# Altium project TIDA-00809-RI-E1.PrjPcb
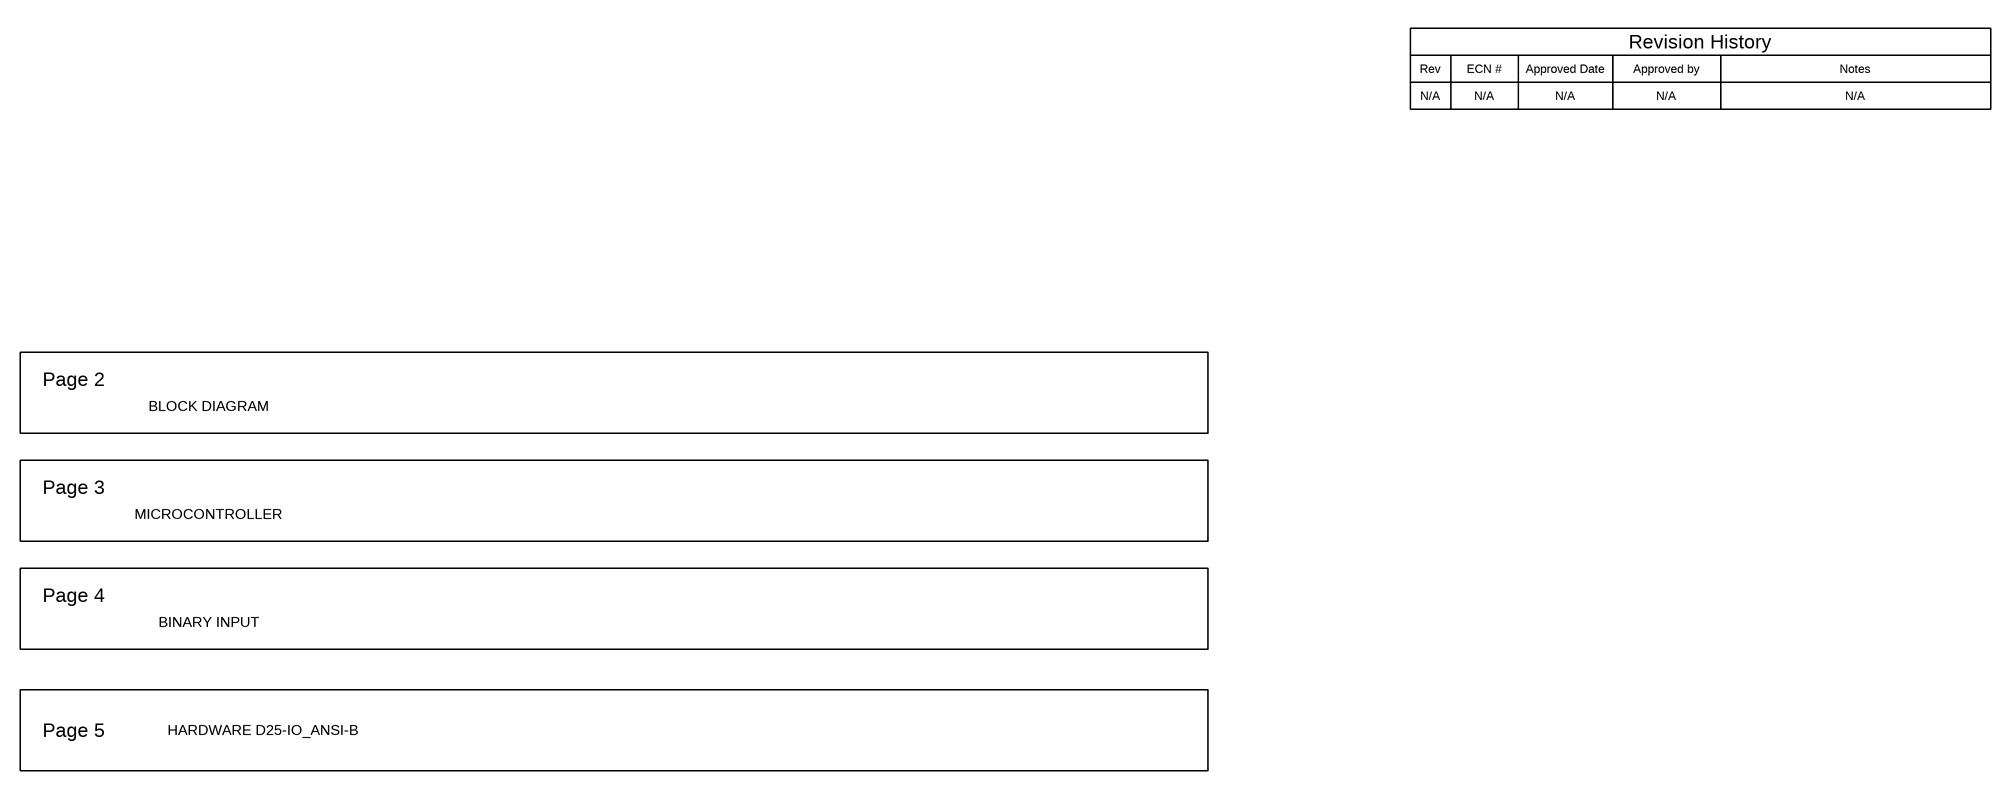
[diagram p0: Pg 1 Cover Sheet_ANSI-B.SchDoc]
TID: 00809-RI; TechSupport: http://www.ti.com/support; SCH_Rev: E1; PRJ_Title: AC/DC BINARY INPUT; PRJ_Number: TIDA-00809-RI; PRJ_Engineer: Sreenivas; PRJ_Customer: Public Release; PCB_Rev: E1; PCB_Layout: Avinash N; EVM_Orderable: N/A; CopyrightYear: 2016
5 sheets, 168 parts. Net scope: flat (ports and power ports of the same name join across sheets).
Board file: TIDA-00809-RI-E1.PcbDoc
Sheets:
  Pg 1 Cover Sheet_ANSI-B.SchDoc
  Pg2 Block Diagram.SchDoc
  Pg3 MICROCONTROLLER.SchDoc
  Pg 4 BINARY INPUTS.SchDoc
  Pg 5 Hardware_ANSI-B.SchDoc

## Sheet Pg 1 Cover Sheet_ANSI-B.SchDoc: Block Diagram
size 431 x 279 mm; Date: Not shown in title block; ApprovedBy: Not shown in title block; CheckedBy: Not shown in title block; Author: Not shown in title block; CompanyName: Not shown in title block; DrawnBy: Sreenivas; Engineer: Sreenivas; Organization: Not shown in title block; Address1: Not shown in title block; Address2: Not shown in title block; Address3: Not shown in title block; Address4: Not shown in title block; DocumentNumber: 1; Revision: Use project parameter SCH_Rev; SheetNumber: 1; SheetTotal: 5; PageSetup: Record=PageOptions¦CenterHorizontal=True¦CenterVertical=True¦PrintScale=1.00¦XCorrection=1.00¦YCorrection=1.00¦PrintKind=0¦BorderSize=5000000¦LeftOffset=0¦BottomOffset=0¦Orientation=2¦PaperLength=1000¦PaperWidth=1000¦Scale=100¦PaperSource=15¦PrintQuality=600¦MediaType=1¦DitherType=10¦PaperKind=Letter¦PrintScaleMode=1

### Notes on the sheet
- Rev
- N/A
- ECN #
- Approved Date
- Approved by
- Revision History
- Notes
- Page 2
- BLOCK DIAGRAM
- Page 3
- MICROCONTROLLER
- Page 4
- BINARY INPUT
- Page 5
- HARDWARE D25-IO_ANSI-B

## Sheet Pg2 Block Diagram.SchDoc: Block Diagram
size 431 x 279 mm; Date: Not shown in title block; ApprovedBy: Not shown in title block; CheckedBy: Not shown in title block; Author: Not shown in title block; CompanyName: Not shown in title block; DrawnBy: Sreenivas; Engineer: Sreenivas; Organization: Not shown in title block; Address1: Not shown in title block; Address2: Not shown in title block; Address3: Not shown in title block; Address4: Not shown in title block; DocumentNumber: 1; Revision: Use project parameter SCH_Rev; SheetNumber: 2; SheetTotal: 5; PageSetup: Record=PageOptions¦CenterHorizontal=True¦CenterVertical=True¦PrintScale=1.00¦XCorrection=1.00¦YCorrection=1.00¦PrintKind=0¦BorderSize=5000000¦LeftOffset=0¦BottomOffset=0¦Orientation=2¦PaperLength=1000¦PaperWidth=1000¦Scale=100¦PaperSource=15¦PrintQuality=600¦MediaType=1¦DitherType=10¦PaperKind=Letter¦PrintScaleMode=1
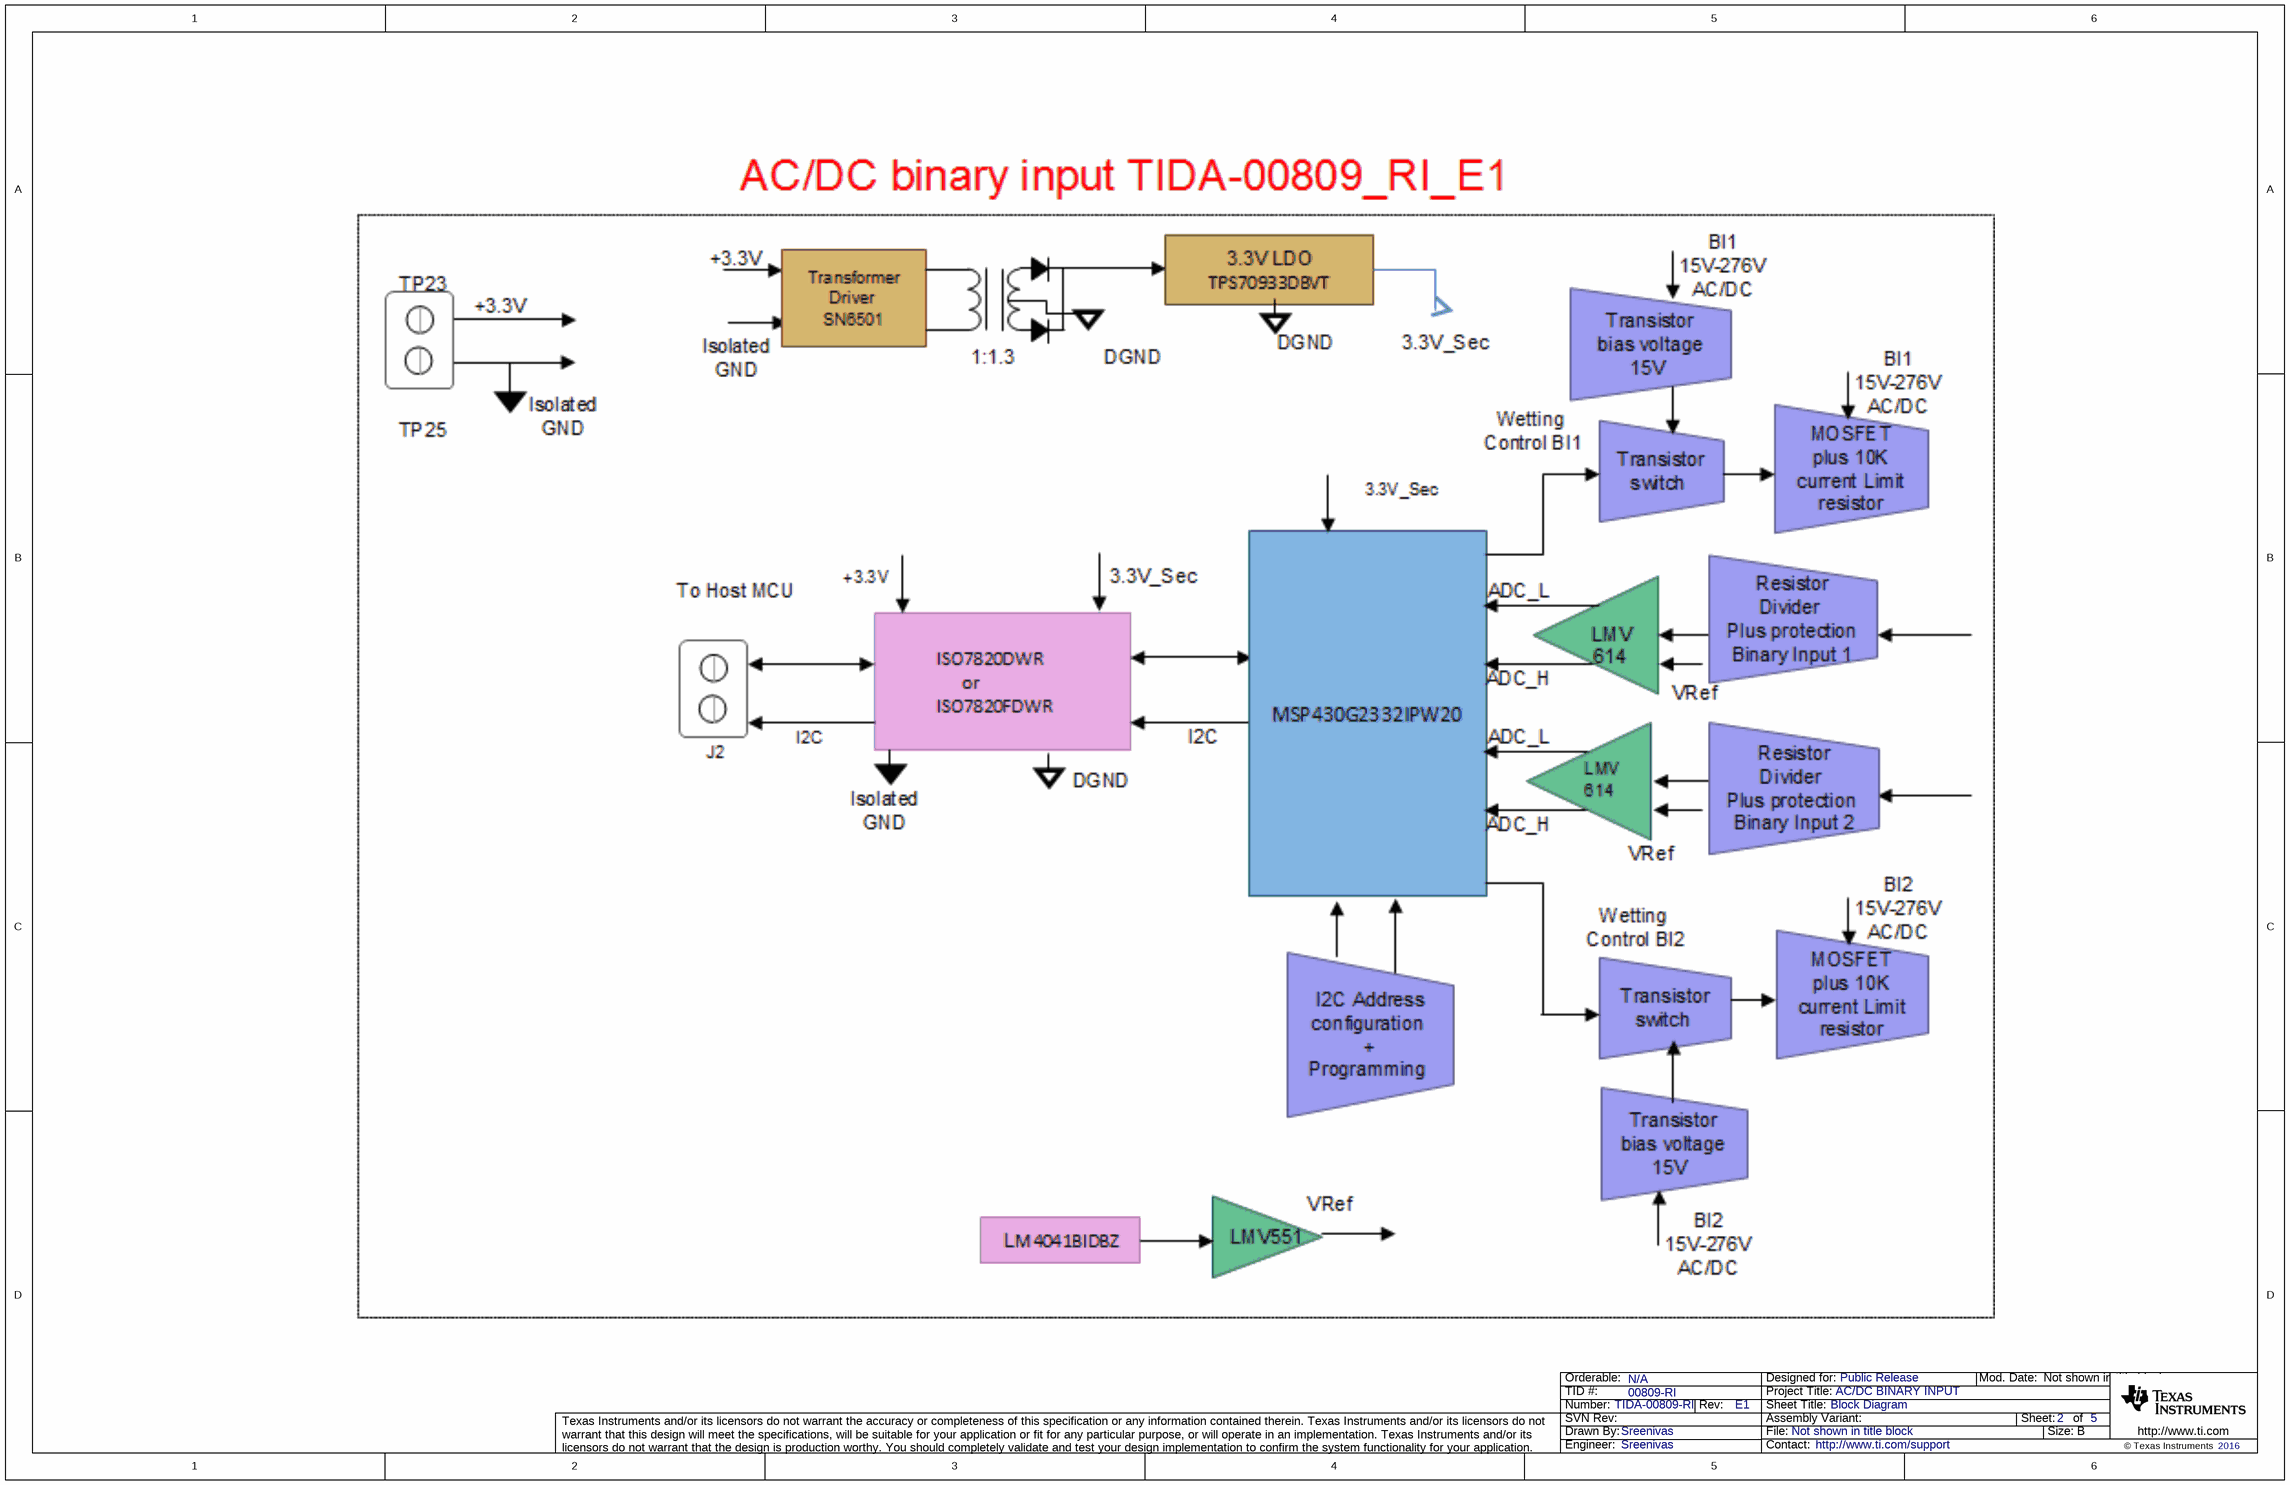
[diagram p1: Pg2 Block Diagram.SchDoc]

## Sheet Pg3 MICROCONTROLLER.SchDoc: Block Diagram
size 431 x 279 mm; Date: Not shown in title block; ApprovedBy: Not shown in title block; CheckedBy: Not shown in title block; Author: Not shown in title block; CompanyName: Not shown in title block; DrawnBy: Sreenivas; Engineer: Sreenivas; Organization: Not shown in title block; Address1: Not shown in title block; Address2: Not shown in title block; Address3: Not shown in title block; Address4: Not shown in title block; DocumentNumber: 1; Revision: Use project parameter SCH_Rev; SheetNumber: 3; SheetTotal: 5; PageSetup: Record=PageOptions¦CenterHorizontal=True¦CenterVertical=True¦PrintScale=1.00¦XCorrection=1.00¦YCorrection=1.00¦PrintKind=0¦BorderSize=5000000¦LeftOffset=0¦BottomOffset=0¦Orientation=2¦PaperLength=1000¦PaperWidth=1000¦Scale=100¦PaperSource=15¦PrintQuality=600¦MediaType=1¦DitherType=10¦PaperKind=Letter¦PrintScaleMode=1
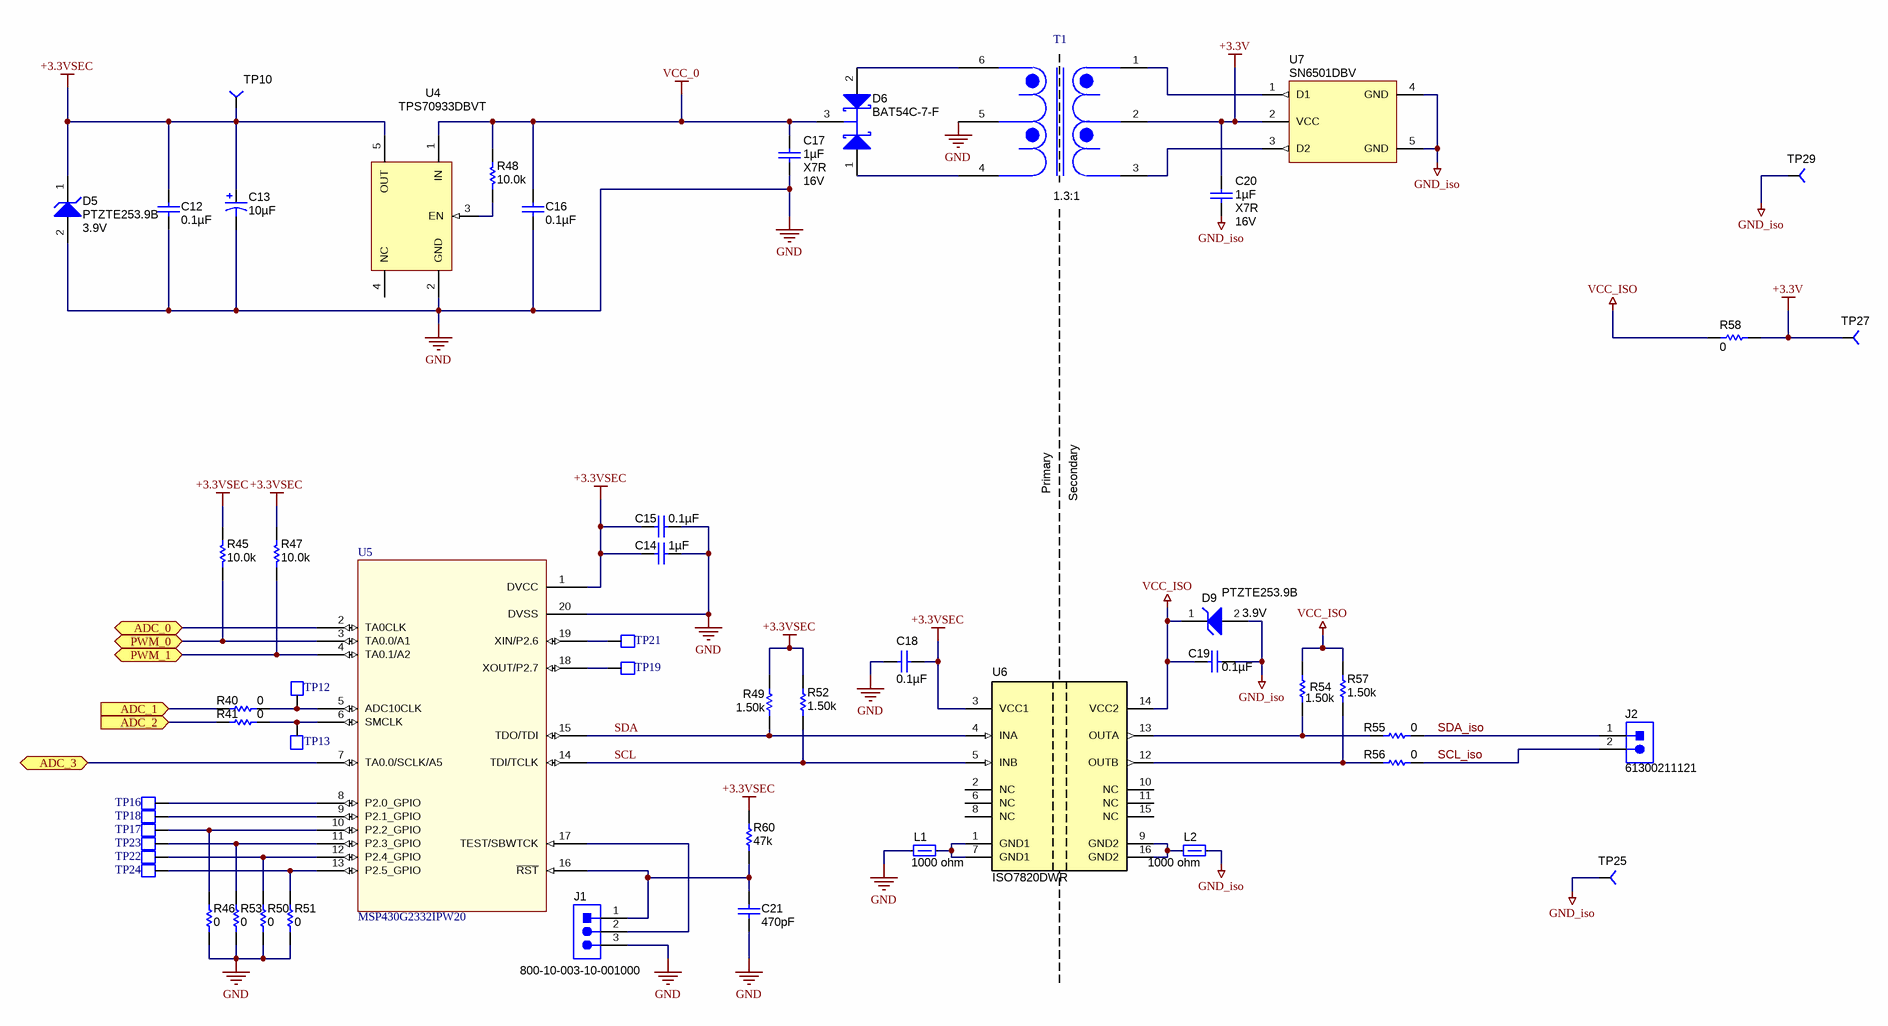
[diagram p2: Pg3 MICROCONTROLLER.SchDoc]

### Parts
C12  ValueDisplayed: 0.1µF  [0603]  (hidden comment: C0603C104K5RACTU)
C13  ValueDisplayed: 10µF  [3528-21]  (hidden comment: T491B106K016AT)
C14  ValueDisplayed: 1µF  [0603]  (hidden comment: C1608X7R1C105K)
C15  ValueDisplayed: 0.1µF  [0603]  (hidden comment: C0603C104K5RACTU)
C16  ValueDisplayed: 0.1µF  [0603]  (hidden comment: C0603C104K5RACTU)
C17  ValueDisplayed: 1µF  Value2: 16V  TempCo: X7R  [0603]  (hidden comment: C1608X7R1C105K)
C18  ValueDisplayed: 0.1µF  [0603]  (hidden comment: C0603C104K5RACTU)
C19  ValueDisplayed: 0.1µF  [0603]  (hidden comment: C0603C104K5RACTU)
C20  ValueDisplayed: 1µF  Value2: 16V  TempCo: X7R  [0603]  (hidden comment: C1608X7R1C105K)
C21  ValueDisplayed: 470pF  [0603]  (hidden comment: GRM188R71H471KA01D)
D5  PTZTE253.9B  value 3.9V  [SMA]
D6  BAT54C-7-F  [SOT-23]
D9  PTZTE253.9B  value 3.9V  [SMA]
J1  800-10-003-10-001000  [Mill-Max_800-10-003-10-001000]
J2  61300211121  [WURTH_61300211121]
L1  value 1000 ohm  [1206]  (hidden comment: HZ1206D102R-10)
L2  value 1000 ohm  [1206]  (hidden comment: HZ1206D102R-10)
R40  ValueDisplayed: 0  [0603]  (hidden comment: CRCW06030000Z0EA)
R41  ValueDisplayed: 0  [0603]  (hidden comment: CRCW06030000Z0EA)
R45  value 10.0k  [0603]  (hidden comment: CRCW060310K0FKEA)
R46  ValueDisplayed: 0  [0402]  (hidden comment: RC0402JR-070RL)
R47  value 10.0k  [0603]  (hidden comment: CRCW060310K0FKEA)
R48  value 10.0k  [0603]  (hidden comment: CRCW060310K0FKEA)
R49  value 1.50k  [0603]  (hidden comment: CRCW06031K50FKEA)
R50  ValueDisplayed: 0  [0402]  (hidden comment: RC0402JR-070RL)
R51  ValueDisplayed: 0  [0402]  (hidden comment: RC0402JR-070RL)
R52  value 1.50k  [0603]  (hidden comment: CRCW06031K50FKEA)
R53  ValueDisplayed: 0  [0402]  (hidden comment: RC0402JR-070RL)
R54  value 1.50k  [0603]  (hidden comment: CRCW06031K50FKEA)
R55  ValueDisplayed: 0  [0603]  (hidden comment: CRCW06030000Z0EA)
R56  ValueDisplayed: 0  [0603]  (hidden comment: CRCW06030000Z0EA)
R57  value 1.50k  [0603]  (hidden comment: CRCW06031K50FKEA)
R58  ValueDisplayed: 0  [0603]  (hidden comment: CRCW06030000Z0EA)
R60  ValueDisplayed: 47k  [0603]  (hidden comment: RC0603JR-0747KL)
T1  (no value)  [Wurth_750313734]
TP10  TP1_PD40_D0.5_S50  [TP1_PD40_D0.5_S50]  (value not drawn)
TP12  PAD_230UM  [PAD_230UM]  (value not drawn)
TP13  PAD_230UM  [PAD_230UM]  (value not drawn)
TP16  PAD_230UM  [PAD_230UM]  (value not drawn)
TP17  PAD_230UM  [PAD_230UM]  (value not drawn)
TP18  PAD_230UM  [PAD_230UM]  (value not drawn)
TP19  PAD_230UM  [PAD_230UM]  (value not drawn)
TP21  PAD_230UM  [PAD_230UM]  (value not drawn)
TP22  PAD_230UM  [PAD_230UM]  (value not drawn)
TP23  PAD_230UM  [PAD_230UM]  (value not drawn)
TP24  PAD_230UM  [PAD_230UM]  (value not drawn)
TP25  TP-5001-BLACK  [TH-40]  (value not drawn)
TP27  TP-5001-BLACK  [TH-40]  (value not drawn)
TP29  TP-5001-BLACK  [TH-40]  (value not drawn)
U4  TPS70933DBVT  [DBV0005A_N]
U5  MSP430G2332IPW20  [PW0020A_N]
U6  ISO7820DWR  [DW0016B_N]
U7  SN6501DBV  [DBV0005A_N]

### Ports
ADC_0 (bidir), ADC_1 (in), ADC_2 (in), ADC_3 (bidir), PWM_0 (bidir), PWM_1 (bidir)

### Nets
+3.3V: C20.1 R58.2 T1.2 TP27.1 U7.2(VCC)
+3.3VSEC: C12.1 C13.1(+) C14.1 C15.2 C18.2 D5.1(K) R45.2 R47.2 R49.2 R52.2 R60.2 TP10.1 U4.5(OUT) U5.1(DVCC) U6.3(VCC1)
GND: C12.2 C13.2(-) C14.2 C15.1 C16.2 C17.2 C18.1 C21.2 D5.2(A) J1.3 L1.1 R46.1 R50.1 R51.1 R53.1 T1.5 U4.2(GND) U5.20(DVSS)
GND_iso: C19.2 C20.2 D9.2(A) L2.2 TP25.1 TP29.1 U7.4(GND) U7.5(GND)
VCC_0: C16.1 C17.1 D6.3(K) R48.2 U4.1(IN)
VCC_ISO: C19.1 D9.1(K) R54.2 R57.2 R58.1 U6.14(VCC2)
ADC_0: U5.2(TA0CLK) ; port ADC_0
ADC_1: R40.1 ; port ADC_1
ADC_2: R41.1 ; port ADC_2
ADC_3: U5.7(TA0.0/SCLK/A5) ; port ADC_3
PWM_0: R45.1 U5.3(TA0.0/A1) ; port PWM_0
PWM_1: R47.1 U5.4(TA0.1/A2) ; port PWM_1
SCL: R52.1 U5.14(TDI/TCLK) U6.5(INB)
SCL_iso: J2.2 R56.2
SDA: R49.1 U5.15(TDO/TDI) U6.4(INA)
SDA_iso: J2.1 R55.2
NetC21_1: C21.1 J1.1 R60.1 U5.16(~{RST})
NetD6_1: D6.1(A1) T1.4
NetD6_2: D6.2(A2) T1.6
NetJ1_2: J1.2 U5.17(TEST/SBWTCK)
NetL1_2: L1.2 U6.1(GND1) U6.7(GND1)
NetL2_1: L2.1 U6.9(GND2) U6.16(GND2)
NetR40_2: R40.2 TP12.1 U5.5(ADC10CLK)
NetR41_2: R41.2 TP13.1 U5.6(SMCLK)
NetR46_2: R46.2 TP17.1 U5.10(P2.2_GPIO)
NetR48_1: R48.1 U4.3(EN)
NetR50_2: R50.2 TP22.1 U5.12(P2.4_GPIO)
NetR51_2: R51.2 TP24.1 U5.13(P2.5_GPIO)
NetR53_2: R53.2 TP23.1 U5.11(P2.3_GPIO)
NetR54_1: R54.1 R55.1 U6.13(OUTA)
NetR56_1: R56.1 R57.1 U6.12(OUTB)
NetT1_1: T1.1 U7.1(D1)
NetT1_3: T1.3 U7.3(D2)
NetTP16_1: TP16.1 U5.8(P2.0_GPIO)
NetTP18_1: TP18.1 U5.9(P2.1_GPIO)
NetTP19_1: TP19.1 U5.18(XOUT/P2.7)
NetTP21_1: TP21.1 U5.19(XIN/P2.6)

Not connected (* = marked no-connect by the designer): U4 4(NC); U6 2(NC) 6(NC) 8(NC) 10(NC) 11(NC) 15(NC)

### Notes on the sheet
- (near T1) 1.3:1
- Primary
- Secondary

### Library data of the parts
C12 C15 C16 C18 C19 = C0603C104K5RACTU: CAP, CERM, 0.1uF, 50V, +/-10%, X7R, 0603; Manufacturer: Kemet; Polarized: N; CompType: Capacitor; U/M: EA; Cap_F: 0.0000001; Tolerance_%: 10; Value1: Unknown; VDC_V: 50; TaMin_C: -55; TaMax_C: 125
C13 = 293D106X9016B2TE3: CAP, TA, 10 µF, 16 V, +/- 10%, 2 ohm, SMD; Manufacturer: Vishay-Sprague; Polarized: Y; CompType: Capacitor; Value: 10uF; U/M: EA; Cap_F: 0.00001; Tolerance_%: 10; Value1: 2 ohm; VDC_V: 16; Value2: 16V; ESR_ohm: 2; IRMS_A: 0.21; TaMin_C: -55; TaMax_C: 125; Cap_Case: B
C14 C17 C20 = C1608X7R1C105K: CAP, CERM, 1uF, 16V, +/-10%, X7R, 0603; Manufacturer: TDK; Polarized: N; CompType: Capacitor; U/M: EA; Cap_F: 0.000001; Tolerance_%: 10; ESR_Ohm: 0.0057; Value1: 0.0057 ohm; VDC_V: 16; TaMin_C: -55; TaMax_C: 125
C21 = GRM188R71H471KA01D: CAP, CERM, 470 pF, 50 V, +/- 10%, X7R, 0603; Manufacturer: MuRata; Polarized: N; CompType: Capacitor; Value: 470pF; U/M: EA; Cap_F: 0.00000000047; Tolerance_%: 10; Value1: Unknown; VDC_V: 50; Value2: 50V; TaMin_C: -55; TaMax_C: 125
D5 D9 = PTZTE255.6B: DIODE ZENER 4.1V 1W PMDS; Manufacturer: Rohm Semiconductor; U/M: EA; Vz_V: 3.9
D6 = BAT54C-7-F: Diode, Schottky, 30V, 0.2A, SOT-23; Manufacturer: Diodes Inc.; U/M: EA; Vf_V: 0.65; Value2: 0.65V; Io_A: 0.2; Vr_V: 30; TJmax_C: 125
J1 = 800-10-003-10-001000: Header, 100mil, 3x1, TH; Manufacturer: Mill-Max; SymbolCreator: a0799628; U/M: EA
J2 = 61300211121: Header, 2.54 mm, 2x1, Gold, TH; Manufacturer: Wurth Elektronik; SymbolCreator: a0412235
L1 L2 = HZ1206D102R-10: Ferrite Bead, 1000 ohm @ 100 MHz, 0.4 A, 1206; Manufacturer: Laird-Signal Integrity Products; Imax_A: 0.4; Value1: 0.4 ohm; Value2: 0.4A; ZTyp@100MHz_Ohm: 1000; Ztyp@1GHz_Ohm: 100
R40 R41 R55 R56 R58 = CRCW06030000Z0EA: RES, 0, 5%, 0.1 W, 0603; Manufacturer: Vishay-Dale; CompType: Resistor; Value: 0; Value_Code: 0000; Tolerance_%: 5; Power_W: 0.1; Value2: 0.1W; VDC_V: 75; TempCo: 200 ppm/C; EIA_Code: E24; U/M: EA
R45 R47 R48 = CRCW060310K0FKEA: RES, 10.0k ohm, 1%, 0.1W, 0603; Manufacturer: Vishay-Dale; CompType: Resistor; Res_ohm: 10000; Value_Code: 10k0; Tolerance_%: 1; Power_W: 0.1; VDC_V: 75; TempCo: 100 ppm/C; EIA_Code: E96; U/M: EA
R46 R50 R51 R53 = CRCW06030000Z0EA: RES, 0, 5%, 0.063 W, 0402; Manufacturer: Yageo; CompType: Resistor; Value: 0; Value_Code: 0000; Tolerance_%: 5; Power_W: 0.1; Value2: 0.1W; VDC_V: 75; TempCo: 200 ppm/C; EIA_Code: E24; U/M: EA
R49 R52 R54 R57 = CRCW06031K50FKEA: RES, 1.50k ohm, 1%, 0.1W, 0603; Manufacturer: Vishay-Dale; CompType: Resistor; Res_ohm: 1500; Value_Code: 1k50; Tolerance_%: 1; Power_W: 0.1; VDC_V: 75; TempCo: 100 ppm/C; EIA_Code: E96; U/M: EA
R60 = RC0603JR-0747KL: RES, 47 k, 5%, 0.1 W, 0603; Manufacturer: Yageo America; CompType: Resistor; Value: 47k; Res_ohm: 47000; Value_Code: 47k0; Tolerance_%: 5; Power_W: 0.1; Value2: 0.1W; VDC_V: 50; TempCo: 100 ppm/C; EIA_Code: E24; U/M: EA
T1 = 750313734_TRANSFORMER: TRANSFORMER SMD; Manufacturer: Wurth Electronics Midcom; PartNumber: 750313638
TP10 = TP-040_RND: Test Point 40mil pad 20mil drill; Manufacturer: STD; Value: STD
TP12 TP13 TP16-TP19 TP21-TP24 = PAD_230UM: Pad, SMT 0.23 mm; Area: 13200
TP25 TP27 TP29 = TP-5001-BLACK: Test Point,  Black, Thru Hole Color Keyed; Manufacturer: Keystone; PartNumber: 5001; area: 10.000; Value: 5001
U4 = TPS70933DBVT: IC REG LDO 3.3V 0.15A SOT23-5; Alternate Manufacturer: None; Manufacturer: Texas Instruments; SymbolCreator: a0411947; U/M: EA
U5 = MSP430G2332IPW20: IC MCU 16BIT 4KB FLASH 20TSSOP; Manufacturer: TI; Comp Type: Microcontroller
U6 = ISO7820DWR: High-Performance, 8000 VPK Reinforced Dual Channel Digital Isolator, DW0016B; Manufacturer: Texas Instruments; SymbolCreator: Altium; CompType: IC; U/M: EA
U7 = SN6501DBV: Transformer Driver for Isolated Power Supplies, DBV0005A; Alternate Manufacturer: None; Manufacturer: Texas Instruments; SymbolCreator: a0411947; CompType: IC; U/M: EA

## Sheet Pg 4 BINARY INPUTS.SchDoc: Block Diagram
size 431 x 279 mm; Date: Not shown in title block; ApprovedBy: Not shown in title block; CheckedBy: Not shown in title block; Author: Not shown in title block; CompanyName: Not shown in title block; DrawnBy: Sreenivas; Engineer: Sreenivas; Organization: Not shown in title block; Address1: Not shown in title block; Address2: Not shown in title block; Address3: Not shown in title block; Address4: Not shown in title block; DocumentNumber: 1; Revision: Use project parameter SCH_Rev; SheetNumber: 4; SheetTotal: 5; PageSetup: Record=PageOptions¦CenterHorizontal=True¦CenterVertical=True¦PrintScale=1.00¦XCorrection=1.00¦YCorrection=1.00¦PrintKind=0¦BorderSize=5000000¦LeftOffset=0¦BottomOffset=0¦Orientation=2¦PaperLength=1000¦PaperWidth=1000¦Scale=100¦PaperSource=15¦PrintQuality=600¦MediaType=1¦DitherType=10¦PaperKind=Letter¦PrintScaleMode=1
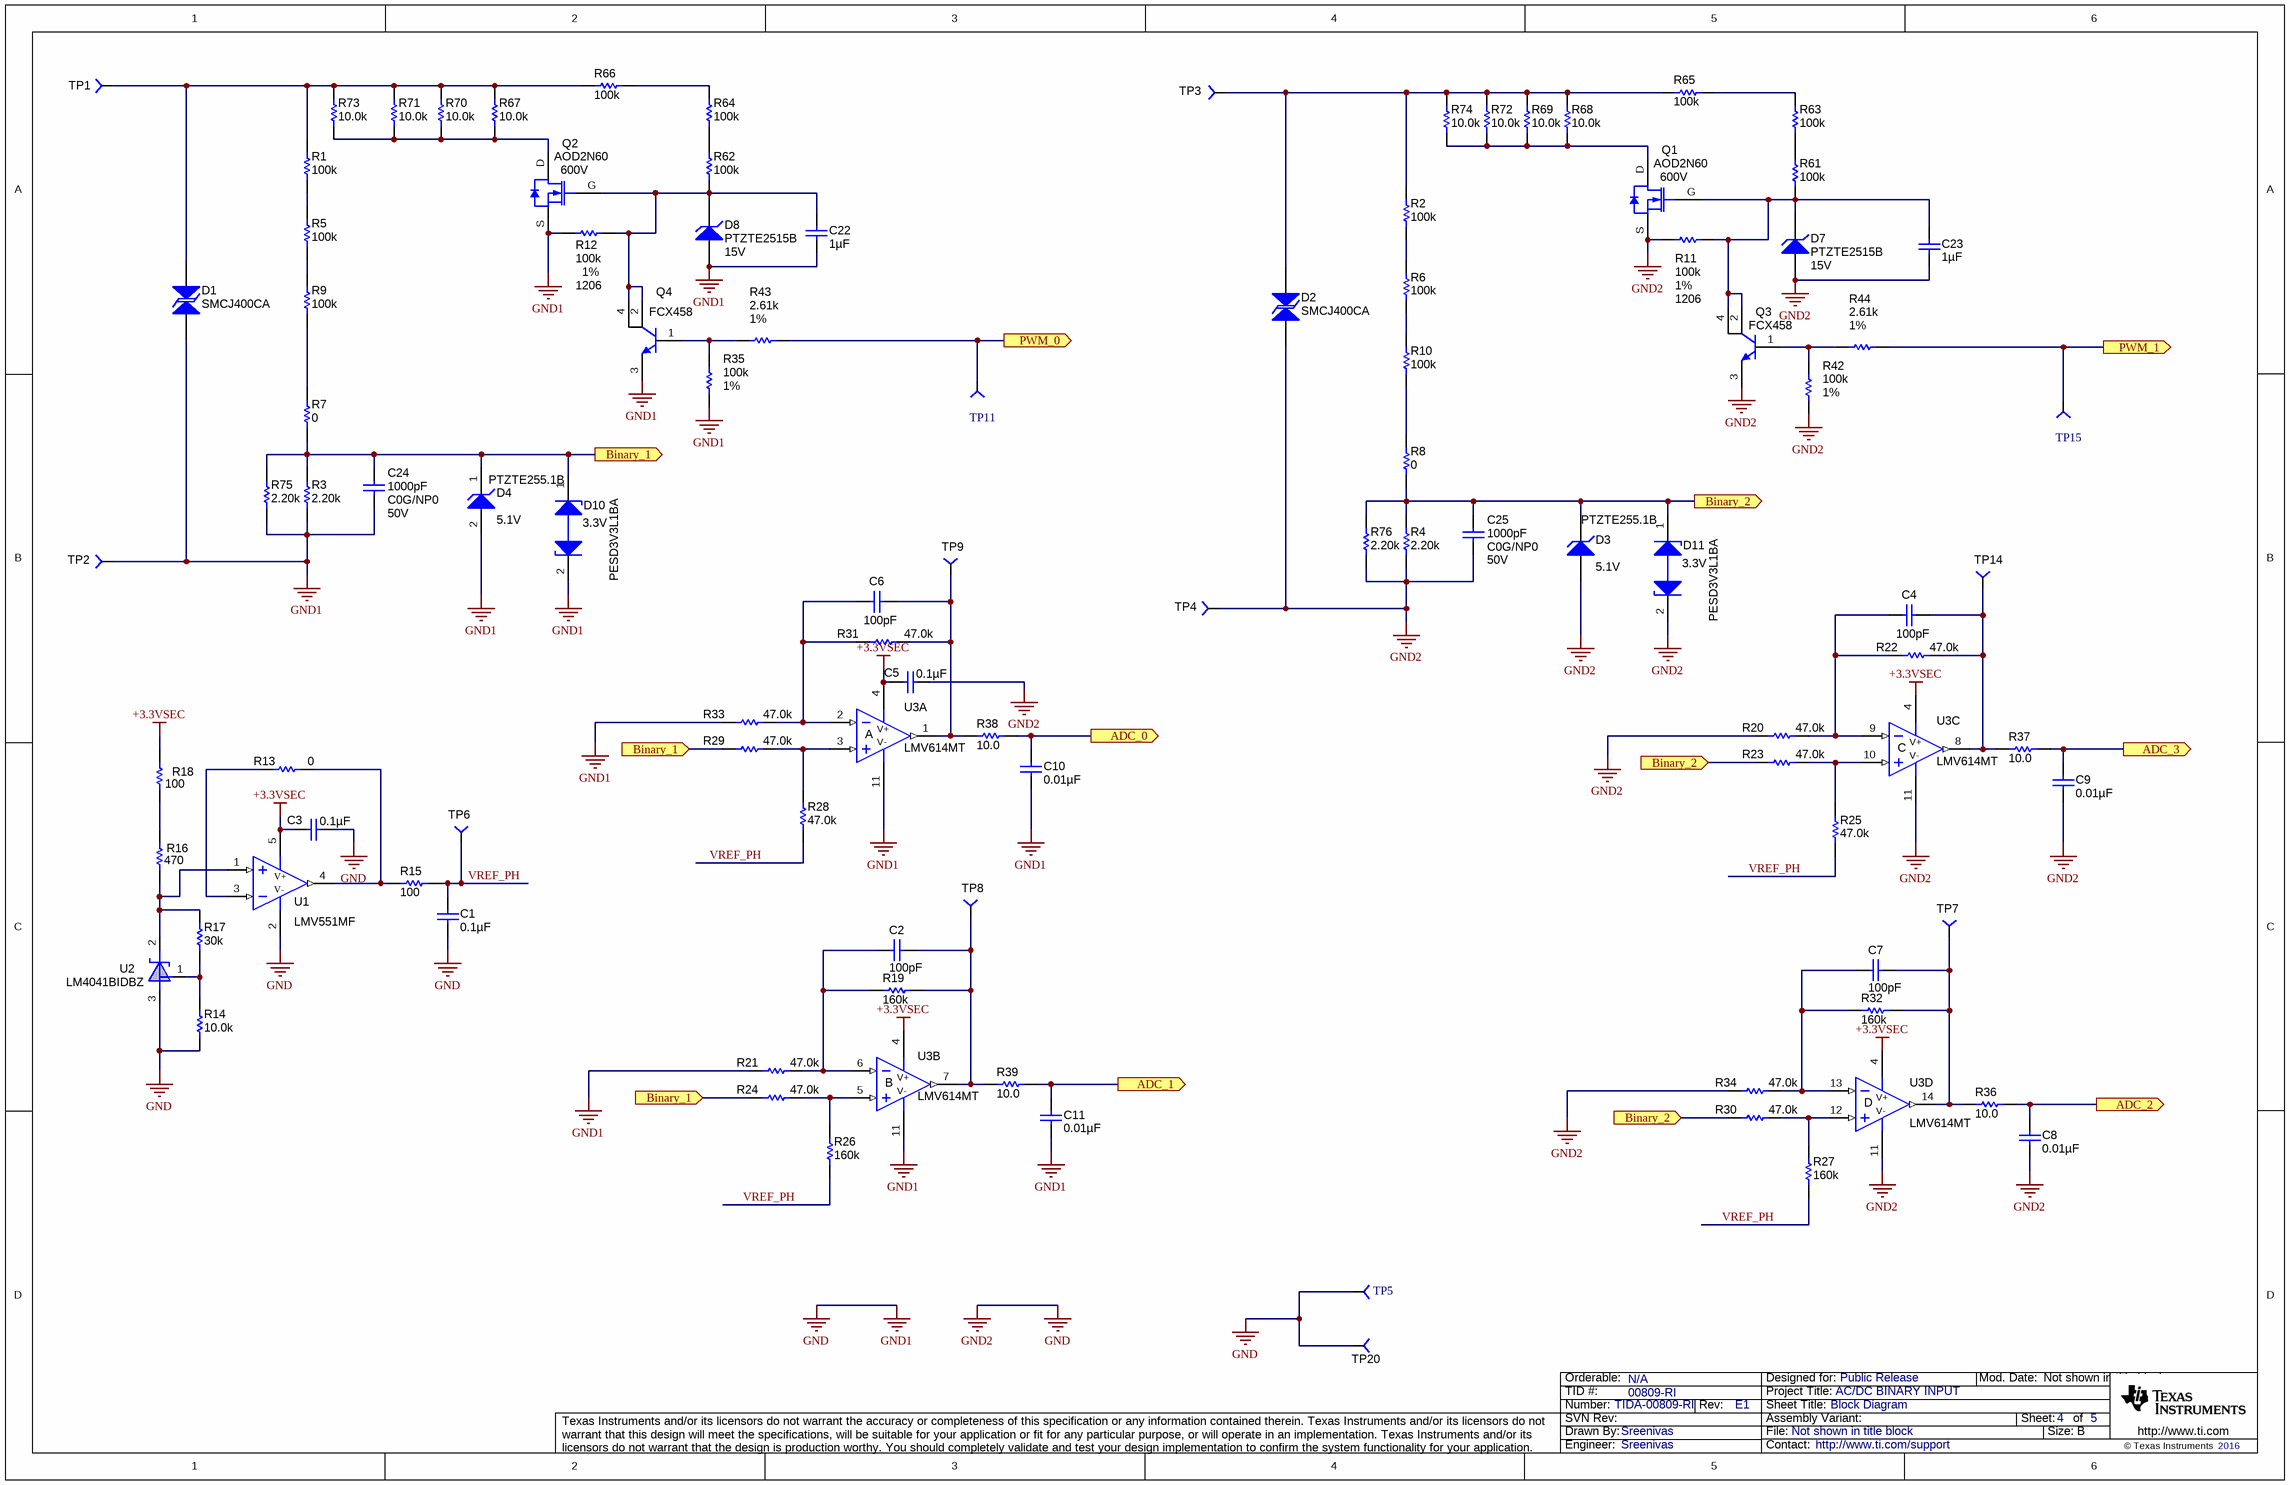
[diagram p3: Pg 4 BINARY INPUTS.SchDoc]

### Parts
C1  ValueDisplayed: 0.1µF  [0603]  (hidden comment: 06033C104JAT2A)
C2  ValueDisplayed: 100pF  [0603]  (hidden comment: 06035A101FAT2A)
C3  ValueDisplayed: 0.1µF  [0603]  (hidden comment: 06033C104JAT2A)
C4  ValueDisplayed: 100pF  [0603]  (hidden comment: 06035A101FAT2A)
C5  ValueDisplayed: 0.1µF  [0603]  (hidden comment: 06033C104JAT2A)
C6  ValueDisplayed: 100pF  [0603]  (hidden comment: 06035A101FAT2A)
C7  ValueDisplayed: 100pF  [0603]  (hidden comment: 06035A101FAT2A)
C8  ValueDisplayed: 0.01µF  [0603]  (hidden comment: C1608C0G1E103J)
C9  ValueDisplayed: 0.01µF  [0603]  (hidden comment: C1608C0G1E103J)
C10  ValueDisplayed: 0.01µF  [0603]  (hidden comment: C1608C0G1E103J)
C11  ValueDisplayed: 0.01µF  [0603]  (hidden comment: C1608C0G1E103J)
C22  ValueDisplayed: 1µF  [0603]  (hidden comment: UMK107AB7105KA-T)
C23  ValueDisplayed: 1µF  [0603]  (hidden comment: UMK107AB7105KA-T)
C24  ValueDisplayed: 1000pF  Value2: 50V  TempCo: C0G/NP0  [0603]  (hidden comment: C1608C0G1H102J)
C25  ValueDisplayed: 1000pF  Value2: 50V  TempCo: C0G/NP0  [0603]  (hidden comment: C1608C0G1H102J)
D1  SMCJ400CA  [SMC]
D2  SMCJ400CA  [SMC]
D3  PTZTE255.1B  value 5.1V  [SMA]
D4  PTZTE255.1B  value 5.1V  [SMA]
D7  PTZTE2515B  value 15V  [SMA]
D8  PTZTE2515B  value 15V  [SMA]
D10  PESD3V3L1BA  value 3.3V  [DIO_SOD323]
D11  PESD3V3L1BA  value 3.3V  [DIO_SOD323]
Q1  AOD2N60  value 600V  [DPAK_G]
Q2  AOD2N60  value 600V  [DPAK_G]
Q3  FCX458  [SOT-89-3]
Q4  FCX458  [SOT-89-3]
R1  ValueDisplayed: 100k  [1206]  (hidden comment: RC1206FR-07100KL)
R2  ValueDisplayed: 100k  [1206]  (hidden comment: RC1206FR-07100KL)
R3  ValueDisplayed: 2.20k  [0603]  (hidden comment: RC0603FR-072K2L)
R4  ValueDisplayed: 2.20k  [0603]  (hidden comment: RC0603FR-072K2L)
R5  ValueDisplayed: 100k  [1206]  (hidden comment: RC1206FR-07100KL)
R6  ValueDisplayed: 100k  [1206]  (hidden comment: RC1206FR-07100KL)
R7  ValueDisplayed: 0  [0603]  (hidden comment: RC0603JR-070RL)
R8  ValueDisplayed: 0  [0603]  (hidden comment: RC0603JR-070RL)
R9  ValueDisplayed: 100k  [1206]  (hidden comment: RC1206FR-07100KL)
R10  ValueDisplayed: 100k  [1206]  (hidden comment: RC1206FR-07100KL)
R11  value 100k  Value1: 1%  [1206]  (hidden comment: CRCW1206100KFKEA)
R12  value 100k  Value1: 1%  [1206]  (hidden comment: CRCW1206100KFKEA)
R13  ValueDisplayed: 0  [0603]  (hidden comment: RC0603JR-070RL)
R14  value 10.0k  [0603]  (hidden comment: CRCW060310K0FKEA)
R15  value 100  [0603]  (hidden comment: CRCW0603100RFKEA)
R16  value 470  [0603]  (hidden comment: CRCW0603470RJNEA)
R17  value 30k  [0603]  (hidden comment: CRCW060330K0JNEA)
R18  value 100  [0603]  (hidden comment: CRCW0603100RFKEA)
R19  ValueDisplayed: 160k  [0603]  (hidden comment: CRCW0603160KFKEA)
R20  ValueDisplayed: 47.0k  [0603]  (hidden comment: RC0603FR-0747KL)
R21  ValueDisplayed: 47.0k  [0603]  (hidden comment: RC0603FR-0747KL)
R22  ValueDisplayed: 47.0k  [0603]  (hidden comment: RC0603FR-0747KL)
R23  ValueDisplayed: 47.0k  [0603]  (hidden comment: RC0603FR-0747KL)
R24  ValueDisplayed: 47.0k  [0603]  (hidden comment: RC0603FR-0747KL)
R25  ValueDisplayed: 47.0k  [0603]  (hidden comment: RC0603FR-0747KL)
R26  ValueDisplayed: 160k  [0603]  (hidden comment: CRCW0603160KFKEA)
R27  ValueDisplayed: 160k  [0603]  (hidden comment: CRCW0603160KFKEA)
R28  ValueDisplayed: 47.0k  [0603]  (hidden comment: RC0603FR-0747KL)
R29  ValueDisplayed: 47.0k  [0603]  (hidden comment: RC0603FR-0747KL)
R30  ValueDisplayed: 47.0k  [0603]  (hidden comment: RC0603FR-0747KL)
R31  ValueDisplayed: 47.0k  [0603]  (hidden comment: RC0603FR-0747KL)
R32  ValueDisplayed: 160k  [0603]  (hidden comment: CRCW0603160KFKEA)
R33  ValueDisplayed: 47.0k  [0603]  (hidden comment: RC0603FR-0747KL)
R34  ValueDisplayed: 47.0k  [0603]  (hidden comment: RC0603FR-0747KL)
R35  value 100k  Value1: 1%  [0603]  (hidden comment: CRCW0603100KFKEA)
R36  ValueDisplayed: 10.0  [0603]  (hidden comment: CRCW060310R0FKEA)
R37  ValueDisplayed: 10.0  [0603]  (hidden comment: CRCW060310R0FKEA)
R38  ValueDisplayed: 10.0  [0603]  (hidden comment: CRCW060310R0FKEA)
R39  ValueDisplayed: 10.0  [0603]  (hidden comment: CRCW060310R0FKEA)
R42  value 100k  Value1: 1%  [0603]  (hidden comment: CRCW0603100KFKEA)
R43  value 2.61k  Value1: 1%  [0603]  (hidden comment: CRCW06032K61FKEA)
R44  value 2.61k  Value1: 1%  [0603]  (hidden comment: CRCW06032K61FKEA)
R61  ValueDisplayed: 100k  [1206]  (hidden comment: RC1206FR-07100KL)
R62  ValueDisplayed: 100k  [1206]  (hidden comment: RC1206FR-07100KL)
R63  ValueDisplayed: 100k  [1206]  (hidden comment: RC1206FR-07100KL)
R64  ValueDisplayed: 100k  [1206]  (hidden comment: RC1206FR-07100KL)
R65  ValueDisplayed: 100k  [1206]  (hidden comment: RC1206FR-07100KL)
R66  ValueDisplayed: 100k  [1206]  (hidden comment: RC1206FR-07100KL)
R67  ValueDisplayed: 10.0k  [1206]  (hidden comment: MCR18ERTF1002)
R68  ValueDisplayed: 10.0k  [1206]  (hidden comment: MCR18ERTF1002)
R69  ValueDisplayed: 10.0k  [1206]  (hidden comment: MCR18ERTF1002)
R70  ValueDisplayed: 10.0k  [1206]  (hidden comment: MCR18ERTF1002)
R71  ValueDisplayed: 10.0k  [1206]  (hidden comment: MCR18ERTF1002)
R72  ValueDisplayed: 10.0k  [1206]  (hidden comment: MCR18ERTF1002)
R73  ValueDisplayed: 10.0k  [1206]  (hidden comment: MCR18ERTF1002)
R74  ValueDisplayed: 10.0k  [1206]  (hidden comment: MCR18ERTF1002)
R75  ValueDisplayed: 2.20k  [0603]  (hidden comment: RC0603FR-072K2L)
R76  ValueDisplayed: 2.20k  [0603]  (hidden comment: RC0603FR-072K2L)
TP1  TP-5001-BLACK  [TH-40]  (value not drawn)
TP2  TP-5001-BLACK  [TH-40]  (value not drawn)
TP3  TP-5001-BLACK  [TH-40]  (value not drawn)
TP4  TP-5001-BLACK  [TH-40]  (value not drawn)
TP5  TP-040_RND  [TP-040_RND]  (value not drawn)
TP6  TP-040_RND  [TP-040_RND]  (value not drawn)
TP7  TP-040_RND  [TP-040_RND]  (value not drawn)
TP8  TP-040_RND  [TP-040_RND]  (value not drawn)
TP9  TP-040_RND  [TP-040_RND]  (value not drawn)
TP11  TP-040_RND  [TP-040_RND]  (value not drawn)
TP14  TP-040_RND  [TP-040_RND]  (value not drawn)
TP15  TP-040_RND  [TP-040_RND]  (value not drawn)
TP20  TP1_PD40_D0.5_S50  [TP1_PD40_D0.5_S50]  (value not drawn)
U1  LMV551MF  [MF05A_L]
U2  LM4041BIDBZ  [SOT-23]
U3  LMV614MT  [PW0014A_N]  (parts A,B,C,D of 4)

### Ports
ADC_0 (out), ADC_1 (out), ADC_2 (out), ADC_3 (out), Binary_1 (in), Binary_1 (out), Binary_2 (in), Binary_2 (out), PWM_0 (out), PWM_1 (out)

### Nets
+3.3VSEC: C3.2 C5.2 R18.1 U1.5(V+) U3.4(V+)
GND: C1.1 C3.1 C5.1 C8.1 C9.1 C10.1 C11.1 C22.1 C23.1 C24.1 C25.1 D1.1 D2.1 D3.2(A) D4.2(A) D7.2(A) D8.2(A) D10.2(K) D11.2(K) Q1.S Q2.S Q3.3(E) Q4.3(E) R3.1 R4.1 R11.1 R12.1 R14.1 R20.1 R21.1 R33.2 R34.1 R35.1 R42.1 R75.1 R76.1 TP2.1 TP4.1 TP5.1 TP20.1 U1.2(V-) U2.3(A) U3.11(V-)  [also labelled GND1, GND2]
ADC_0: C10.2 R38.2 ; port ADC_0
ADC_1: C11.2 R39.2 ; port ADC_1
ADC_2: C8.2 R36.2 ; port ADC_2
ADC_3: C9.2 R37.2 ; port ADC_3
Binary_1: C24.2 D4.1(K) D10.1(K) R3.2 R7.2 R24.1 R29.2 R75.2 ; port Binary_1
Binary_2: C25.2 D3.1(K) D11.1(K) R4.2 R8.2 R23.1 R30.1 R76.2 ; port Binary_2
PWM_0: R43.1 TP11.1 ; port PWM_0
PWM_1: R44.1 TP15.1 ; port PWM_1
VREF_PH: C1.2 R15.2 R25.1 R26.1 R27.1 R28.1 TP6.1
NetC2_1: C2.1 R19.1 R39.1 TP8.1 U3.7(OUT)
NetC2_2: C2.2 R19.2 R21.2 U3.6(IN-)
NetC4_1: C4.1 R22.2 R37.1 TP14.1 U3.8(OUT)
NetC4_2: C4.2 R20.2 R22.1 U3.9(IN-)
NetC6_1: C6.1 R31.1 R38.1 TP9.1 U3.1(OUT)
NetC6_2: C6.2 R31.2 R33.1 U3.2(IN-)
NetC7_1: C7.1 R32.1 R36.1 TP7.1 U3.14(OUT)
NetC7_2: C7.2 R32.2 R34.2 U3.13(IN-)
NetC22_2: C22.2 D8.1(K) Q2.G Q4.2(C) Q4.4(C) R12.2 R62.2
NetC23_2: C23.2 D7.1(K) Q1.G Q3.2(C) Q3.4(C) R11.2 R61.1
NetD1_2: D1.2 R1.1 R66.1 R67.2 R70.2 R71.2 R73.2 TP1.1
NetD2_2: D2.2 R2.1 R65.1 R68.2 R69.2 R72.2 R74.2 TP3.1
NetQ1_D: Q1.D R68.1 R69.1 R72.1 R74.1
NetQ2_D: Q2.D R67.1 R70.1 R71.1 R73.1
NetQ3_1: Q3.1(B) R42.2 R44.2
NetQ4_1: Q4.1(B) R35.2 R43.2
NetR1_2: R1.2 R5.1
NetR2_2: R2.2 R6.1
NetR5_2: R5.2 R9.1
NetR6_2: R6.2 R10.1
NetR7_1: R7.1 R9.2
NetR8_1: R8.1 R10.2
NetR13_1: R13.1 U1.3(IN-)
NetR13_2: R13.2 R15.1 U1.4(OUT)
NetR14_2: R14.2 R17.1 U2.1(FB)
NetR16_1: R16.1 R17.2 U1.1(IN+) U2.2(C)
NetR16_2: R16.2 R18.2
NetR23_2: R23.2 R25.2 U3.10(IN+)
NetR24_2: R24.2 R26.2 U3.5(IN+)
NetR27_2: R27.2 R30.2 U3.12(IN+)
NetR28_2: R28.2 R29.1 U3.3(IN+)
NetR61_2: R61.2 R63.1
NetR62_1: R62.1 R64.2
NetR63_2: R63.2 R65.2
NetR64_1: R64.1 R66.2

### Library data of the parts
C1 C3 C5 = 06033C104JAT2A: CAP, CERM, 0.1uF, 25V, +/-5%, X7R, 0603; Manufacturer: AVX; Polarized: N; CompType: Capacitor; U/M: EA; Cap_F: 0.0000001; Tolerance_%: 5; ESR_Ohm: 0.05; Value1: 0.05 ohm; VDC_V: 25; TaMin_C: -55; TaMax_C: 125
C2 C4 C6 C7 = 06035A101FAT2A: CAP, CERM, 100pF, 50V, +/-1%, C0G/NP0, 0603; Manufacturer: AVX; Polarized: N; CompType: Capacitor; U/M: EA; Cap_F: 0.0000000001; Tolerance_%: 1; Value1: Unknown; VDC_V: 50; TaMin_C: -55; TaMax_C: 125
C8-C11 = C1608C0G1E103J: CAP, CERM, 0.01uF, 25V, +/-5%, C0G/NP0, 0603; Manufacturer: TDK; Polarized: N; CompType: Capacitor; U/M: EA; Cap_F: 0.00000001; Tolerance_%: 5; Value1: Unknown; VDC_V: 25; TaMin_C: -55; TaMax_C: 125
C22 C23 = UMK107AB7105KA-T: CAP, CERM, 1 µF, 50 V, +/- 10%, X7R, 0603; Manufacturer: Taiyo Yuden; Polarized: N; CompType: Capacitor; Value: 1uF; U/M: EA; Cap_F: 0.000001; Tolerance_%: 10; Value1: Unknown; VDC_V: 50; Value2: 50V; TaMin_C: -55; TaMax_C: 125
C24 C25 = C1608C0G1H102J: CAP, CERM, 1000pF, 50V, +/-5%, C0G/NP0, 0603; Manufacturer: TDK; Polarized: N; CompType: Capacitor; U/M: EA; Cap_F: 0.000000001; Tolerance_%: 5; ESR_Ohm: 0.0563; Value1: 0.0563 ohm; VDC_V: 50; TaMin_C: -55; TaMax_C: 125
D1 D2 = SMCJ15CA: TVS DIODE 400VWM 648VC SMC; Manufacturer: Littelfuse Inc; Power_W: 1500; Value: 15V
D3 D4 = BZT52C3V3T-7: DIODE ZENER 5.4V 1W PMDS; Manufacturer: Rohm Semiconductor; SymbolCreator: a0412235; U/M: EA; Power_W: 0.3; RJA_CperW: 417
D7 D8 = BZT52C3V3T-7: DIODE ZENER 15.4V 1W PMDS; Manufacturer: Rohm Semiconductor; SymbolCreator: a0412235; U/M: EA; Power_W: 0.3; Vz_V: 5.1V; RJA_CperW: 417
D10 D11 = PESD3V3L1BA: DIODE, TVS, BIDIRECTIONAL, 3.3VWM, 26VC, SOD323; Manufacturer: NXP Semiconductor; SymbolCreator: x0199378
Q1 Q2 = DN2450K4-G: MOSFET N-CH 600V 2A TO252; Manufacturer: Alpha & Omega; Alternate Manufacturer: None; U/M: EA; ChType: N; VdsMax_V: 600; Value1: 10 ohm
Q3 Q4 = FCX458TA, Diodes Inc.: Transistor, NPN, 400V, 500mA, SOT-89; CompType: BJT; PNP: 0; NPN: 1; Vceo_V: 100; Vcesat1_V: 0.6; Value: 0.6V; Value1: 1A; HfeMax: 300; TaMin_C: -65; TaMax_C: 150; U/M: EA
R1 R2 R5 R6 R9 R10 R61-R66 = RC1206FR-07100KL: RES, 100 k, 1%, 0.25 W, 1206; Manufacturer: Yageo America; CompType: Resistor; Value: 100k; Res_ohm: 100000; Tolerance_%: 1; Power_W: 0.25; Value2: 0.25W; VDC_V: 200; TempCo: 100 ppm/C; EIA_Code: E96; U/M: EA
R3 R4 R75 R76 = RC0603FR-072K2L: RES, 2.20 k, 1%, 0.1 W, 0603; Manufacturer: Yageo America; CompType: Resistor; Value: 2.20k; Res_ohm: 2200; Value_Code: 2k20; Tolerance_%: 1; Power_W: 0.1; Value2: 0.1W; VDC_V: 150; TempCo: 200 ppm/C; U/M: EA
R7 R8 R13 = RC0603JR-070RL: RES, 0, 5%, 0.1 W, 0603; Manufacturer: Yageo America; CompType: Resistor; Value: 0; Value_Code: 0000; Tolerance_%: 5; Power_W: 0.1; Value2: 0.1W; VDC_V: 50; TempCo: 200 ppm/C; EIA_Code: E24; U/M: EA
R11 R12 = CRCW1206100KFKEA: RES, 100k ohm, 1%, 0.25W, 1206; Manufacturer: Vishay-Dale; CompType: Resistor; Res_ohm: 100000; Tolerance_%: 1; Power_W: 0.25; VDC_V: 200; TempCo: 100 ppm/C; EIA_Code: E96; U/M: EA
R14 = CRCW060310K0FKEA: as R45 on sheet Pg3 MICROCONTROLLER
R15 R18 = CRCW0603100RFKEA: RES, 100 ohm, 1%, 0.1W, 0603; Manufacturer: Vishay-Dale; CompType: Resistor; Value_Code: 100R; Tolerance_%: 1; Power_W: 0.1; VDC_V: 75; TempCo: 100 ppm/C; EIA_Code: E96; U/M: EA
R16 = CRCW0603470RJNEA: RES, 470 ohm, 5%, 0.1W, 0603; Manufacturer: Vishay-Dale; CompType: Resistor; Value_Code: 470R; Tolerance_%: 5; Power_W: 0.1; VDC_V: 75; TempCo: 200 ppm/C; EIA_Code: E24; U/M: EA
R17 = CRCW060330K0JNEA: RES, 30k ohm, 5%, 0.1W, 0603; Manufacturer: Vishay-Dale; CompType: Resistor; Res_ohm: 30000; Value_Code: 30k0; Tolerance_%: 5; Power_W: 0.1; VDC_V: 75; TempCo: 200 ppm/C; EIA_Code: E24; U/M: EA
R19 R26 R27 R32 = CRCW0603160KFKEA: RES, 160 k, 1%, 0.1 W, 0603; Manufacturer: Vishay-Dale; CompType: Resistor; Value: 160k; Res_ohm: 160000; Tolerance_%: 1; Power_W: 0.1; Value2: 0.1W; VDC_V: 75; TempCo: 100 ppm/C; U/M: EA
R20-R25 R28-R31 R33 R34 = RC0603FR-0747KL: RES, 47.0 k, 1%, 0.1 W, 0603; Manufacturer: Yageo America; CompType: Resistor; Value: 47.0k; Res_ohm: 47000; Value_Code: 47k0; Tolerance_%: 1; Power_W: 0.1; Value2: 0.1W; VDC_V: 150; TempCo: 200 ppm/C; U/M: EA
R35 R42 = CRCW0603100KFKEA: RES, 100k ohm, 1%, 0.1W, 0603; Manufacturer: Vishay-Dale; CompType: Resistor; Res_ohm: 100000; Tolerance_%: 1; Power_W: 0.1; VDC_V: 75; TempCo: 100 ppm/C; EIA_Code: E96; U/M: EA
R36-R39 = CRCW060310R0FKEA: RES, 10.0, 1%, 0.1 W, 0603; Manufacturer: Vishay-Dale; CompType: Resistor; Value: 10.0; Res_ohm: 10; Value_Code: 10R0; Tolerance_%: 1; Power_W: 0.1; Value2: 0.1W; VDC_V: 75; TempCo: 100 ppm/C; EIA_Code: E96; U/M: EA
R43 R44 = CRCW06032K61FKEA: RES, 2.61k ohm, 1%, 0.1W, 0603; Manufacturer: Vishay-Dale; CompType: Resistor; Res_ohm: 2610; Value_Code: 2k61; Tolerance_%: 1; Power_W: 0.1; VDC_V: 75; TempCo: 100 ppm/C; EIA_Code: E96; U/M: EA
R67-R74 = RC1206FR-0727KL: RES SMD 10K OHM 1% 1/4W 1206; Manufacturer: Rohm Semiconductor; CompType: Resistor; Res_ohm: 27000; Value_Code: 10k0; Tolerance_%: 1; Power_W: 0.25; Value2: 0.25W; VDC_V: 200; TempCo: 100 ppm/C; U/M: EA
TP1-TP4 = TP-5001-BLACK: as TP25 on sheet Pg3 MICROCONTROLLER
TP5-TP9 TP11 TP14 TP15 = TP-040_RND: Test Point, O.040 Hole; Manufacturer: STD; Value: STD
TP20 = TP-040_RND: as TP10 on sheet Pg3 MICROCONTROLLER
U1 = LMV551MF: 3MHz Single Micropower R-R Out Op Amp; Manufacturer: TI; Characteristics: LMV551MF 3MHz Single Micropower R-R Out Op Amp; CompType: OpAmp IC; TaMin_C: -40.0; TaMax_C: 125.0; PowerWise: N
U2 = LM4041BIDBZ: IC, Micropower Shunt Voltage Reference 100 ppm/°C, 45µA-12mA,  Adjustable; Manufacturer: TI; Alternate Manufacturer: None; Area: 25500
U3 = LMV614MT: Quad 1.4 MHz, Low Power General Purpose, 1.8V Op Amp, PW0014A; Manufacturer: Texas Instruments; SymbolCreator: a0412235; CompType: OpAmp IC

## Sheet Pg 5 Hardware_ANSI-B.SchDoc: Block Diagram
size 431 x 279 mm; Date: Not shown in title block; ApprovedBy: Not shown in title block; CheckedBy: Not shown in title block; Author: Not shown in title block; CompanyName: Not shown in title block; DrawnBy: Sanjay Pithadia; Engineer: Sanjay Pithadia; Organization: Not shown in title block; Address1: Not shown in title block; Address2: Not shown in title block; Address3: Not shown in title block; Address4: Not shown in title block; DocumentNumber: 1; Revision: Use project parameter SCH_Rev; SheetNumber: 5; SheetTotal: 5; PageSetup: Record=PageOptions¦CenterHorizontal=True¦CenterVertical=True¦PrintScale=1.00¦XCorrection=1.00¦YCorrection=1.00¦PrintKind=0¦BorderSize=5000000¦LeftOffset=0¦BottomOffset=0¦Orientation=2¦PaperLength=1000¦PaperWidth=1000¦Scale=100¦PaperSource=15¦PrintQuality=600¦MediaType=1¦DitherType=10¦PaperKind=Letter¦PrintScaleMode=1
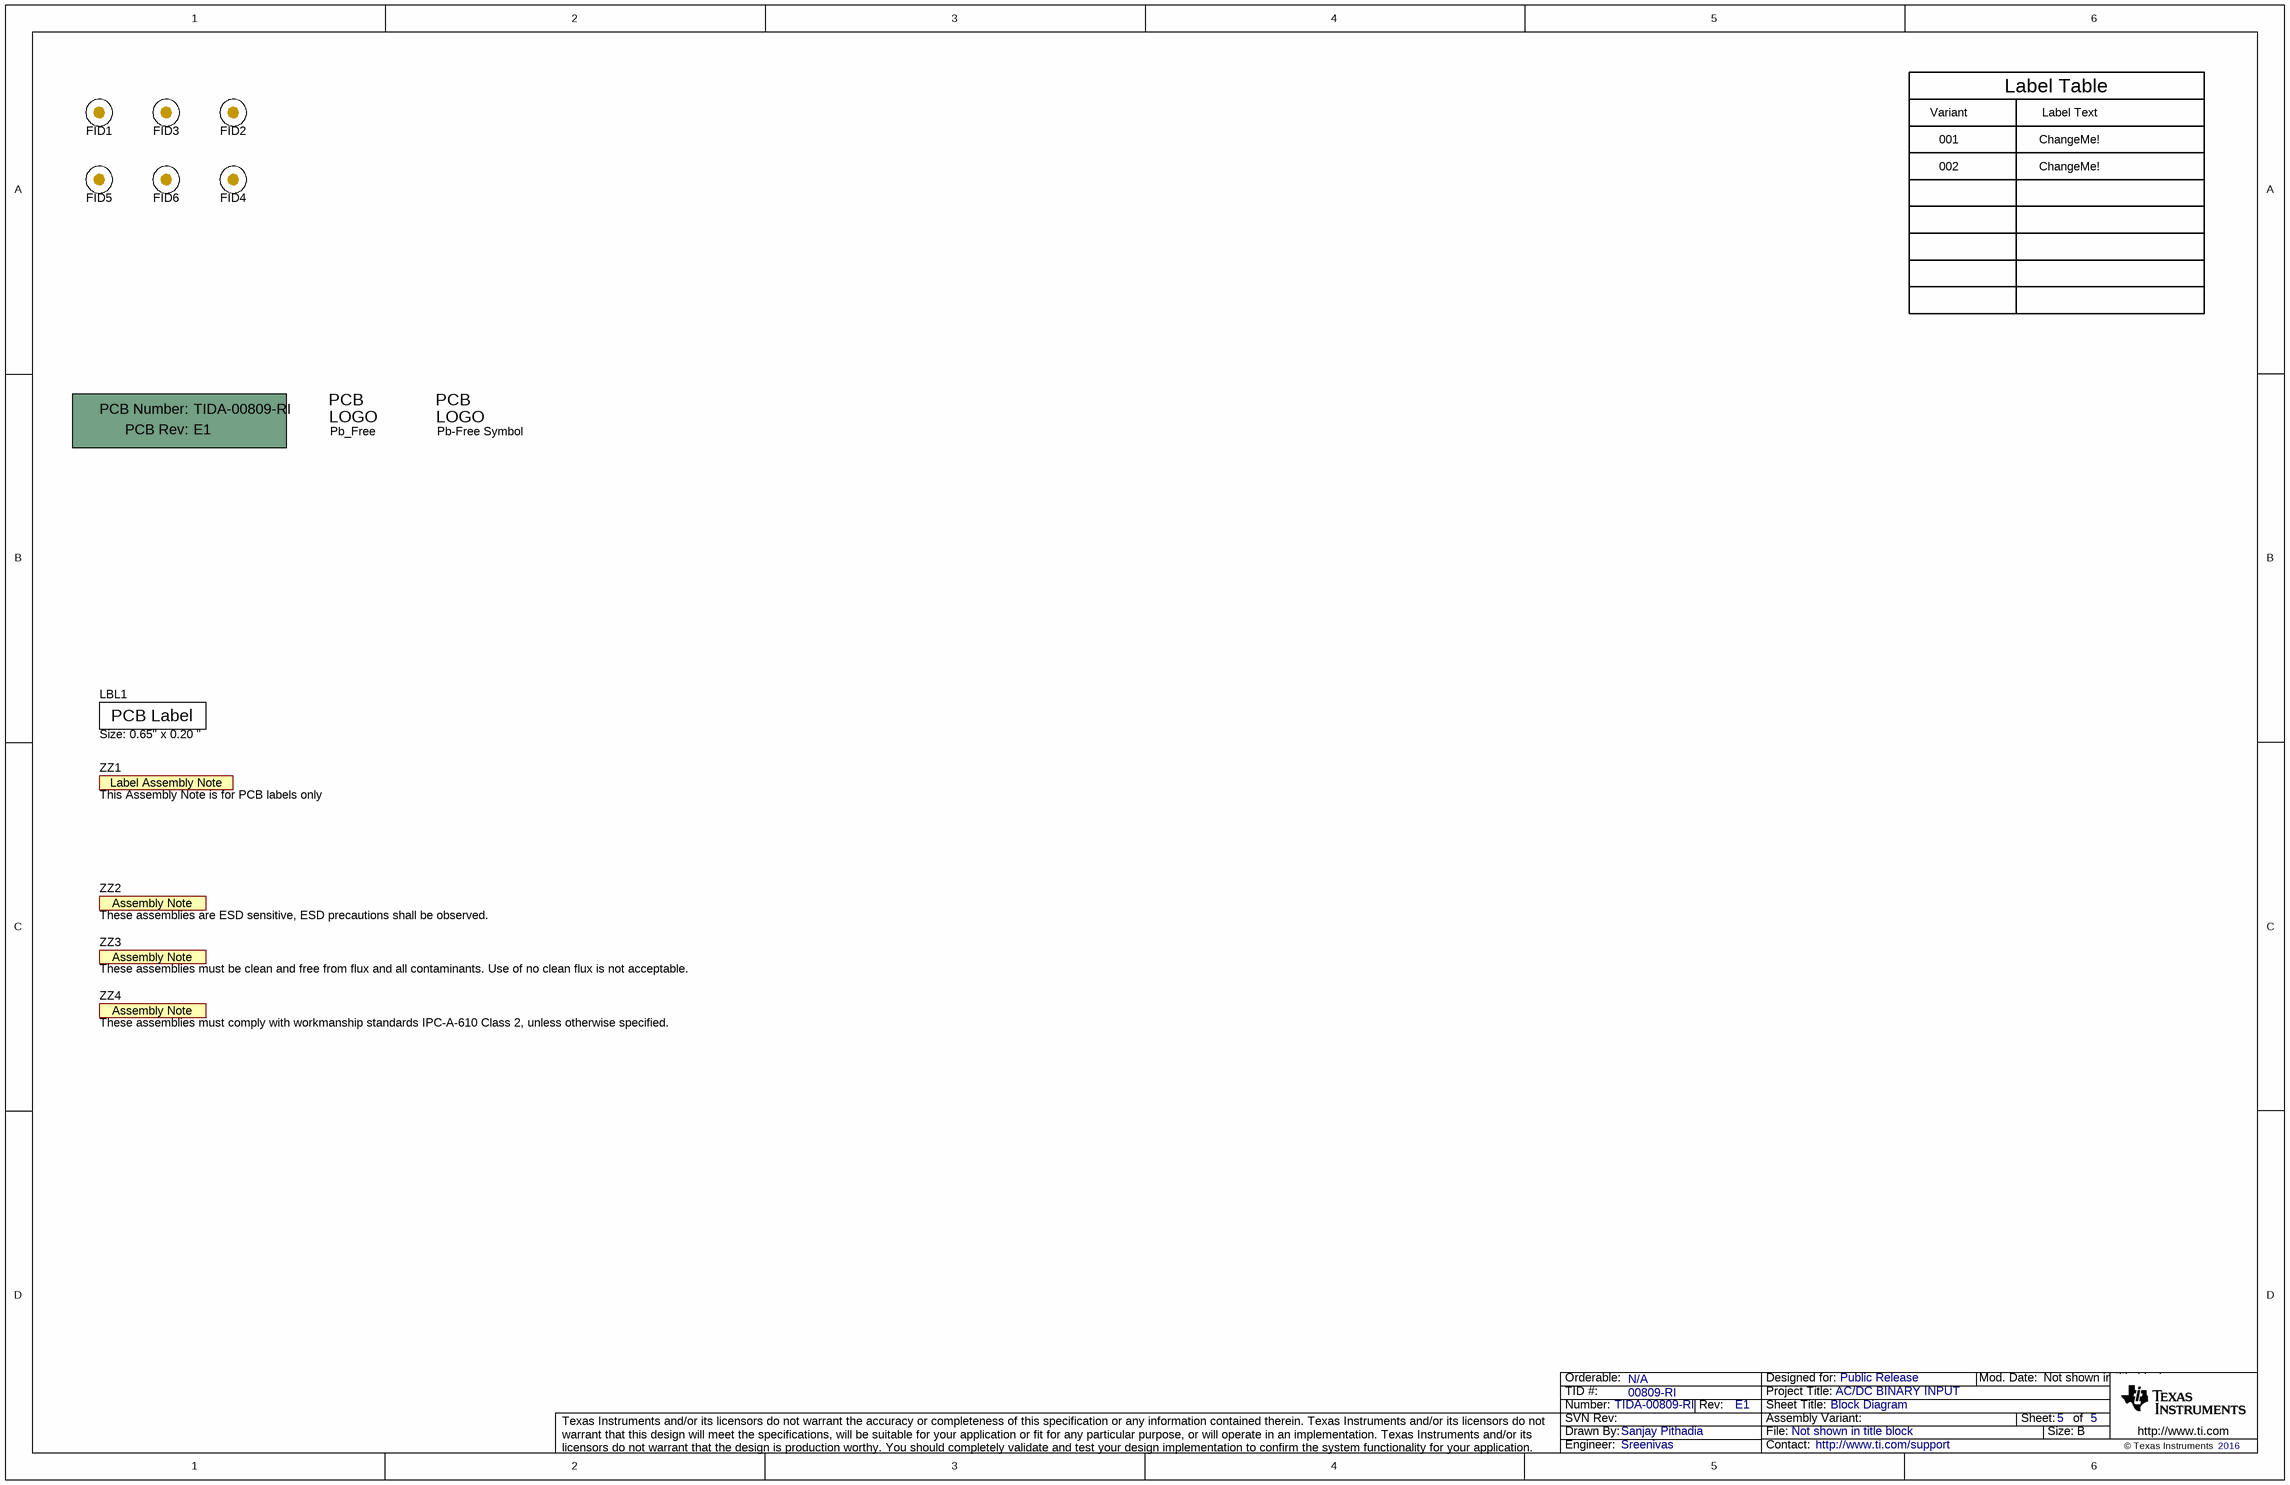
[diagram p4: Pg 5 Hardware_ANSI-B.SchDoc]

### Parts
!PCB1  Printed Circuit Board  (value not drawn)  (mechanical)
FID1  Fiducial  [Fiducial10-20]  (value not drawn)
FID2  Fiducial  [Fiducial10-20]  (value not drawn)
FID3  Fiducial  [Fiducial10-20]  (value not drawn)
FID4  Fiducial  [Fiducial10-20]  (value not drawn)
FID5  Fiducial  [Fiducial10-20]  (value not drawn)
FID6  Fiducial  [Fiducial10-20]  (value not drawn)
LBL1  Size: 0.65" x 0.20 "  [Label_650x200]
Logo3  Pb-Free Symbol  [Pb-Free_Overlay_Small]  (no BOM)
Pb_Free  ESD Susceptible  [ESD_Overlay_small]  (value not drawn)  (no BOM)
ZZ1  This Assembly Note is for PCB labels only  [AssemblyNoteLabel]  (no BOM)
ZZ2  These assemblies are ESD sensitive, ESD precautions shall be observed.  [AssemblyNote]  (no BOM)
ZZ3  These assemblies must be clean and free from flux and all contaminants. Use of no clean flux is not acceptable.  [AssemblyNote]  (no BOM)
ZZ4  These assemblies must comply with workmanship standards IPC-A-610 Class 2, unless otherwise specified.  [AssemblyNote]  (no BOM)

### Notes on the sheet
- Label Table
- Variant
- 001
- 002
- Label Text
- ChangeMe!

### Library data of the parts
!PCB1 = PCB: Manufacturer: Any; PartNumber: TIDA-00809-RI; SymbolCreator: a0412235
FID1-FID6 = Fiducial: Fiducial mark.  There is nothing to buy or mount.; SymbolCreator: codlsc
LBL1 = THT-14-423-10: Thermal Transfer Printable Labels, 0.650" W x 0.200" H - 10,000 per roll; Manufacturer: Brady; SymbolCreator: a0412235; CompType: Label
Logo3 = Pb-Free: SymbolCreator: a0412235
Pb_Free = ESD_Susceptible: ESD Susceptible Symbol; SymbolCreator: a0412235
ZZ1 = AssemblyNoteLabel: SymbolCreator: a0412235
ZZ2-ZZ4 = AssemblyNote: SymbolCreator: codlsc

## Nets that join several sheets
+3.3VSEC: Pg3 MICROCONTROLLER (15 pins), Pg 4 BINARY INPUTS (5 pins)
GND: Pg3 MICROCONTROLLER (18 pins), Pg 4 BINARY INPUTS (43 pins)
ADC_0: Pg3 MICROCONTROLLER (U5.2), Pg 4 BINARY INPUTS (C10.2 R38.2)
ADC_1: Pg3 MICROCONTROLLER (R40.1), Pg 4 BINARY INPUTS (C11.2 R39.2)
ADC_2: Pg3 MICROCONTROLLER (R41.1), Pg 4 BINARY INPUTS (C8.2 R36.2)
ADC_3: Pg3 MICROCONTROLLER (U5.7), Pg 4 BINARY INPUTS (C9.2 R37.2)
PWM_0: Pg3 MICROCONTROLLER (R45.1 U5.3), Pg 4 BINARY INPUTS (R43.1 TP11.1)
PWM_1: Pg3 MICROCONTROLLER (R47.1 U5.4), Pg 4 BINARY INPUTS (R44.1 TP15.1)

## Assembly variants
001: not fitted C24 C25 FID1 FID2 FID3 FID4 FID5 FID6 R45 R46 R47 R49 R50 R51 R52 R53 R54 R57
